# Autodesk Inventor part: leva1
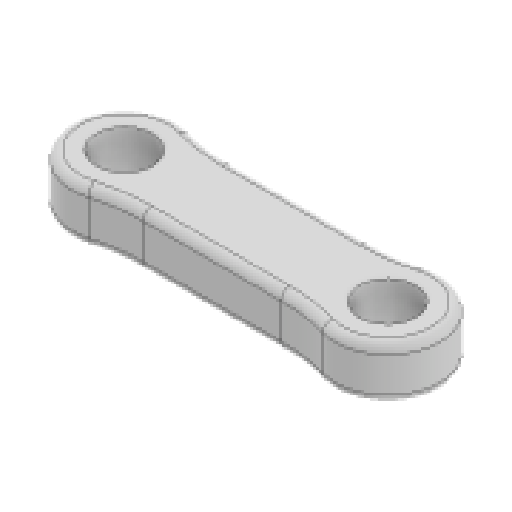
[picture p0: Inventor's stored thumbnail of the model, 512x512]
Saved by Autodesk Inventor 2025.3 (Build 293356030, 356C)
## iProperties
Created: 2026-03
Part Number: leva1
Material: Generico
Document SubType Name: Modeling
Designer: R5800u
Density: 1 g/cm^3
Appearance: Default
Author: R5800u
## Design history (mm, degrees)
sketch "Schizzo1"
  geometry: L1 (7.5, 2.5)-(-7.5, 2.5); L2 (-7.5, 2.5)-(-7.5, -2.5); L3 (-7.5, -2.5)-(7.5, -2.5); L4 (7.5, -2.5)-(7.5, 2.5); L5 (7.5, 2.5)-(-7.5, -2.5); L6 (-7.5, 2.5)-(7.5, -2.5); C1 r 3 at (7.5, 0); C2 r 3 at (-7.5, 0); 5 further points
  constraints: 12 end point, 4 midpoint, 2 centre point, 2 parallel, 1 horizontal, 1 perpendicular
  dimensions: "d0" = 15 distance of L3.end L2.end; "d1" = 5 distance of L2.end L1.end; "d4" = 6 diameter of C1; "d5" = 6 diameter of C2
extrude "Estrusione1" new body sketch "Schizzo1" distance "d2" = 3; taper "d3" = 0 deg
sketch "Schizzo2"
  geometry: A1 r 3 centre (7.5, 0) between (5.842, -2.5) and (5.842, 2.5) reference; A2 r 3 centre (-7.5, 0) between (-5.842, 2.5) and (-5.842, -2.5) reference; 3 further points
  constraints: 2 coincident
hole "Foro1" sketch "Schizzo2" at (7.5, 0), (-7.5, 0) diameter "d6" = 3.2; stored, may be unused: countersink angle "d10" = 90 deg, drill point angle "d12" = 118 deg; dims "d7" = 6, "d8" = 6.5, "d9" = 3.4, "d11" = 8
fillet "Raccordo1" dims "d13" = 10
fillet "Raccordo2" dims "d14" = 0.5
fillet "Raccordo3" dims "d15" = 0.5
node "Solido1"
